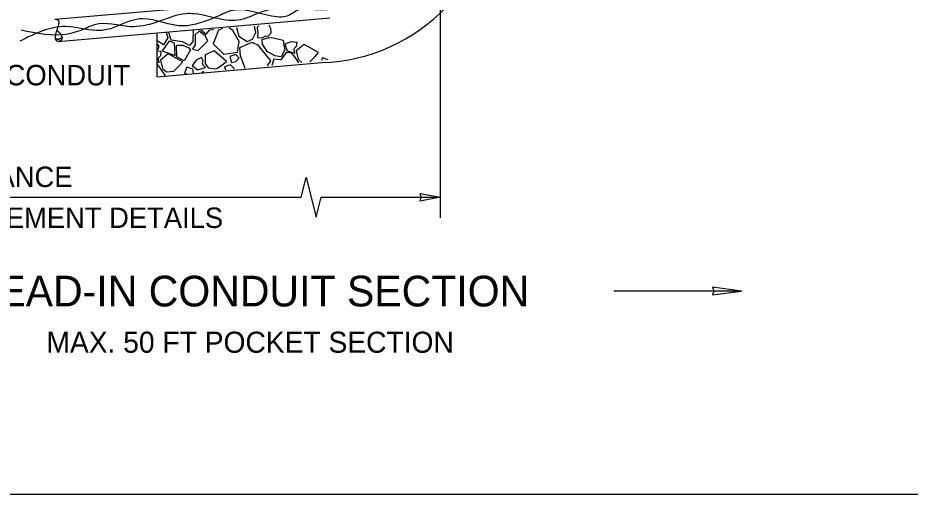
# Model space of a CAD drawing. Extents: x 99862 to 103151, y 100000 to 108153.
# Drawn here: x 101889 to 102587, y 100000 to 100372 of the extents above; entities that cross this region are included whole.
import ezdxf

# ---------------------------------------------------------------- set-up
doc = ezdxf.new("R2010")
doc.units = 0
for name, color, linetype in [('Level 1', 7, 'Continuous'), ('Level 10', 7, 'Continuous'), ('Level 12', 7, 'Continuous'), ('Level 14', 7, 'Continuous'), ('Level 15', 7, 'Continuous'), ('Level 18', 7, 'Continuous'), ('Level 20', 7, 'Continuous'), ('Level 3', 7, 'Continuous'), ('Level 30', 7, 'Continuous'), ('Level 34', 7, 'Continuous')]:
    doc.layers.add(name, color=color, linetype=linetype)

msp = doc.modelspace()

# ---------------------------------------------------------------- linework, layer by layer
at = {"layer": 'Level 1'}
msp.add_lwpolyline([(99862, 99999.5), (103151, 99999.5), (103151, 102075.5), (99862, 102075.5)], close=True, dxfattribs=at)
at = {"layer": 'Level 10'}
for p, q in [((101917.44, 100371.07), (102131.1, 100389.54)), ((101920.05, 100353.73), (102132.64, 100372.11)), ((101997.64, 100326.03), (101997.64, 100360.44)), ((101997.64, 100326.03), (102126.44, 100337.15))]:
    msp.add_line(p, q, dxfattribs=at)
msp.add_arc((102122.02, 100477.27), 140.19, 271.80641, 0.72608, dxfattribs=at)
at = {"layer": 'Level 12'}
for points in [[(102215.84, 100782.45), (102221.83, 100770.84), (102222.26, 100765.43), (102215.28, 100755.18), (102215.28, 100749.99), (102222.79, 100732.97), (102222.79, 100728.93), (102217.14, 100716.2), (102215.56, 100703.64), (102221.65, 100686.22), (102222.81, 100678.94), (102217.47, 100653.33), (102215.88, 100635.58), (102223.94, 100609.75), (102223.94, 100603.4), (102213.55, 100570.79), (102213.55, 100564.45), (102222.62, 100531.63), (102222.05, 100522.64), (102215.57, 100506.44), (102216.29, 100495.34), (102220.82, 100479.43), (102220.33, 100468.35), (102213.26, 100454.4), (102211.15, 100448.92), (102208.41, 100428.39), (102196.89, 100414.83), (102187.15, 100409.34), (102178.2, 100399.1), (102167, 100388.13), (102158.35, 100386.88), (102131.31, 100384.82), (102107.2, 100377.93), (102097.84, 100373.13), (102091.49, 100372.84), (102056.43, 100377.89), (102044.53, 100373.13), (102029.23, 100367.65), (102018.2, 100365.77), (101986.09, 100371.4), (101976.55, 100369.78), (101955.56, 100362.42), (101950.08, 100362.2), (101925.86, 100365.31), (101890.08, 100353.94)], [(102222.34, 100782.45), (102218.33, 100770.19), (102223.09, 100754.41), (102214.77, 100737.67), (102214.77, 100727), (102224.29, 100705.35), (102224.29, 100693.23), (102214.87, 100673.81), (102215.95, 100662.7), (102223.24, 100637.54), (102224.54, 100628.51), (102216.75, 100605.57), (102216.87, 100594.46), (102223.94, 100571.23), (102223.8, 100561.07), (102221.7, 100550.68), (102214.71, 100532.22), (102216.73, 100525), (102220.82, 100504.46), (102221.49, 100497.68), (102216.13, 100475.03), (102217.3, 100466.91), (102218.37, 100455.26), (102216.06, 100447.76), (102208.41, 100437.52), (102201.58, 100427.09), (102194, 100406.26), (102188.74, 100400.61), (102161.97, 100393.83), (102149.56, 100385.1), (102130.79, 100378.47), (102120.92, 100378.4), (102087.72, 100378.8), (102077.64, 100376.16), (102060.47, 100370.24), (102051.38, 100370.39), (102026.13, 100375.29), (102020.5, 100375.37), (101996.48, 100368.51), (101976.34, 100365.23), (101948.49, 100366.75), (101942.67, 100364.37), (101927.72, 100359.42), (101891.02, 100362.52)]]:
    msp.add_spline(points, degree=3, dxfattribs=at)
at = {"layer": 'Level 14'}
for points in [[(102077.07, 100365.81), (102075.68, 100364.56), (102076.26, 100360.21), (102076.09, 100356.68), (102079.62, 100356.51), (102082.66, 100358.07), (102084.43, 100357.7), (102086.77, 100360.54), (102086.56, 100363.86), (102085.18, 100366.36)], [(102004.64, 100360.91), (102005.92, 100356.39), (102002.47, 100350.97), (101997.64, 100354.04)], [(102025.83, 100362.34), (102025.39, 100353.54), (102022.77, 100350.38), (102017.37, 100353.43), (102008.38, 100354.58), (102007.02, 100359.96), (102006.74, 100361.05)], [(102031.78, 100362.75), (102035.82, 100359.26), (102038.76, 100362.66), (102041.41, 100363.03), (102041.69, 100363.42)], [(102048.65, 100363.89), (102045.55, 100362.5), (102041.45, 100351.82), (102049.66, 100343.61), (102053.6, 100344.27), (102060.45, 100345.41), (102061.65, 100353.63), (102056.72, 100362.17), (102053.82, 100364.24)], [(102059.7, 100364.64), (102061.43, 100357.79), (102067.84, 100353.52), (102072.19, 100355.4), (102074.82, 100360.66), (102073.7, 100365.59)], [(102083.81, 100334.61), (102086.37, 100338.6), (102076.59, 100350.84), (102071.5, 100352.97), (102062.06, 100348.78), (102062.39, 100342.71), (102066.07, 100332.85)], [(101997.64, 100347.68), (101998.39, 100347.56), (101999.04, 100350.11), (101997.64, 100351.73)], [(101997.64, 100337.72), (101999.12, 100337.3), (101998.59, 100339.89), (101998.88, 100341.16), (102000.44, 100342.72), (102000.77, 100345.68), (101997.64, 100346.02)], [(102013.36, 100350.72), (102017.72, 100350.68), (102022.23, 100348.74), (102023.62, 100347.17), (102018.62, 100338.4), (102012.81, 100341.64), (102012.54, 100350.39), (102013.36, 100350.72)], [(102117.08, 100337.93), (102117.87, 100338.61), (102120.83, 100341.57), (102123.8, 100345.12), (102117.84, 100348.34), (102112.47, 100351.24), (102106.25, 100346.37), (102107.85, 100339.84), (102110.71, 100337.29)], [(102059.02, 100337.86), (102061.81, 100340.65), (102059.02, 100343.45), (102054.26, 100341.97), (102055.74, 100337.21), (102055.74, 100337.21), (102059.02, 100337.86)], [(102108.35, 100337.06), (102105.17, 100341.64), (102102.95, 100344.45), (102098.44, 100344.92), (102094.25, 100339.26), (102088.83, 100339.92), (102087.15, 100334.95)], [(102131.42, 100339.36), (102126.9, 100340.94), (102126.16, 100338.83)], [(102003.23, 100326.59), (102003.79, 100327.4), (101998.95, 100334.37), (101997.64, 100336.03)], [(102025.85, 100328.84), (102025.38, 100332.02), (102020.68, 100333.68), (102019.03, 100328.97), (102019.03, 100328.97), (102020.45, 100328.3)], [(102057.19, 100331.96), (102057.73, 100332.5), (102054.93, 100335.29), (102050.17, 100333.81), (102050.94, 100331.34)], [(102034.24, 100329.68), (102033.8, 100329.99), (102032.27, 100329.48)]]:
    msp.add_lwpolyline(points, dxfattribs=at)
for points in [[(102037.06, 100354.08), (102035.01, 100357.94), (102030.5, 100361.78), (102027.2, 100358.84), (102027.16, 100351.01), (102025.08, 100347.56), (102029.69, 100346.63)], [(102006.66, 100353.68), (102001.57, 100346.46), (102011.59, 100342.68), (102011.01, 100352.45), (102007.32, 100353.85), (102007.32, 100353.85)], [(102088.64, 100356.6), (102096.19, 100354.62), (102096.77, 100350.85), (102097.34, 100347.07), (102094.55, 100341.73), (102089.62, 100342.55), (102083.63, 100345.84), (102080.01, 100351.42), (102079.56, 100355.32), (102084.94, 100356.84)], [(102105.1, 100348.42), (102106.66, 100349.99), (102106.99, 100352.94), (102102.48, 100353.44), (102097.3, 100351.46), (102099.28, 100346.28), (102105.35, 100344.57), (102104.81, 100347.15)], [(102044.52, 100332.88), (102048.08, 100335.09), (102051.78, 100337.87), (102042.15, 100346.41), (102034.98, 100343.09), (102035.05, 100336.37), (102037.42, 100332.99), (102043.13, 100332.16)], [(102011.65, 100331.35), (102014.6, 100334.3), (102017.58, 100337.85), (102006.25, 100343.97), (102000.03, 100339.11), (102001.63, 100332.58), (102004.71, 100329.83), (102010.46, 100330.32)], [(102033.01, 100336.33), (102033.48, 100338.49), (102032.15, 100341.15), (102028.09, 100339.13), (102024.81, 100334.66), (102029.28, 100331.37), (102035.31, 100333.22), (102033.46, 100335.1)]]:
    msp.add_lwpolyline(points, close=True, dxfattribs=at)
at = {"layer": 'Level 15'}
msp.add_line((102454.79, 100158.37), (102354.79, 100158.37), dxfattribs=at)
for points in [[(102219.14, 100215.73), (102219.14, 100403.1)], [(102110.32, 100231.73), (102114.19, 100247.22), (102121.93, 100216.25), (102125.8, 100231.73)], [(101507.87, 100231.73), (102110.32, 100231.73)], [(102125.8, 100231.73), (102219.14, 100231.73)]]:
    msp.add_lwpolyline(points, dxfattribs=at)
for points in [[(102219.14, 100231.73), (102203.42, 100228.65), (102204.15, 100231.73), (102203.42, 100234.82)], [(102454.79, 100158.37), (102431.96, 100161.35), (102433.01, 100158.37), (102431.96, 100155.38)]]:
    msp.add_lwpolyline(points, close=True, dxfattribs=at)
at = {"layer": 'Level 3'}
msp.add_line((101917.67, 100356.1), (101917.67, 100356.1), dxfattribs=at)
at = {"layer": 'Level 30'}
msp.add_lwpolyline([(101922.6, 100358.29), (101922.81, 100357.48)], dxfattribs=at)
for points in [[(101917.53, 100371.05), (101917.58, 100371.06), (101917.77, 100371.1), (101918.11, 100371.11), (101918.52, 100371.07), (101918.94, 100370.96), (101919.36, 100370.79), (101919.77, 100370.53), (101920.16, 100370.17), (101920.5, 100369.68), (101920.64, 100369.26), (101920.69, 100369.01)], [(101922.94, 100356.76), (101922.99, 100356.53), (101923, 100356.08), (101922.86, 100355.51), (101922.63, 100355.03), (101922.34, 100354.64), (101922.01, 100354.33), (101921.66, 100354.08), (101921.28, 100353.9), (101920.89, 100353.76), (101920.5, 100353.69), (101920.09, 100353.69), (101919.69, 100353.74), (101919.31, 100353.88), (101918.93, 100354.11), (101918.57, 100354.44), (101918.27, 100354.9), (101918.04, 100355.48), (101917.91, 100356.19), (101917.87, 100356.99), (101917.93, 100357.82), (101918.07, 100358.66), (101918.26, 100359.51), (101918.47, 100360.33), (101918.71, 100361.14), (101918.96, 100361.94), (101919.23, 100362.74), (101919.5, 100363.53), (101919.77, 100364.3), (101920.02, 100365.09), (101920.27, 100365.88), (101920.48, 100366.67), (101920.66, 100367.46), (101920.76, 100368.26), (101920.73, 100368.77), (101920.69, 100369.01)], [(101920.56, 100361), (101920.41, 100361.14), (101920.1, 100361.42), (101919.6, 100361.85), (101919.22, 100362.18), (101919.01, 100362.36), (101918.97, 100362.4)], [(101921.51, 100360.09), (101921.48, 100360.12), (101921.33, 100360.32), (101921, 100360.65), (101920.66, 100360.93), (101920.48, 100361.08), (101920.47, 100361.09)], [(101922.38, 100358.94), (101922.36, 100358.98), (101922.24, 100359.19), (101921.96, 100359.58), (101921.68, 100359.91), (101921.52, 100360.07), (101921.51, 100360.09)], [(101922.76, 100357.4), (101922.66, 100357), (101922.56, 100356.78), (101922.37, 100356.45), (101922.07, 100356.12), (101921.73, 100355.85), (101921.38, 100355.63), (101920.99, 100355.47), (101920.59, 100355.35), (101920.2, 100355.28), (101919.8, 100355.26), (101919.41, 100355.29), (101919.03, 100355.39), (101918.66, 100355.57), (101918.32, 100355.82), (101918.07, 100356.15), (101917.94, 100356.4), (101917.89, 100356.51)], [(101922.6, 100358.29), (101922.54, 100358.5), (101922.47, 100358.71), (101922.38, 100358.93), (101922.38, 100358.94)]]:
    msp.add_open_spline(points, degree=3, dxfattribs=at)
at = {"layer": 'Level 34'}
msp.add_lwpolyline([(101922.81, 100357.48), (101922.94, 100356.76)], dxfattribs=at)

# ---------------------------------------------------------------- texts
at = {"layer": 'Level 18'}
for s, p in [("50' MAXIMUM DISTANCE", (101679.93, 100239.73)), ('SEE STUB-OUT CONDUIT PLACEMENT DETAILS', (101555.74, 100207.73))]:
    msp.add_text(s, height=16, dxfattribs=at).set_placement(p)
at = {"layer": 'Level 20'}
msp.add_text('TO CONDUIT', height=16, rotation=360, dxfattribs=at).set_placement((101843.3, 100319.32))
for s, height, p in [('LEAD-IN CONDUIT SECTION', 24, (101855.38, 100146.37)), ('MAX. 50 FT POCKET SECTION ', 16.5, (101910.9, 100110.12))]:
    msp.add_text(s, height=height, dxfattribs=at).set_placement(p)

doc.saveas('drawing.dxf')
